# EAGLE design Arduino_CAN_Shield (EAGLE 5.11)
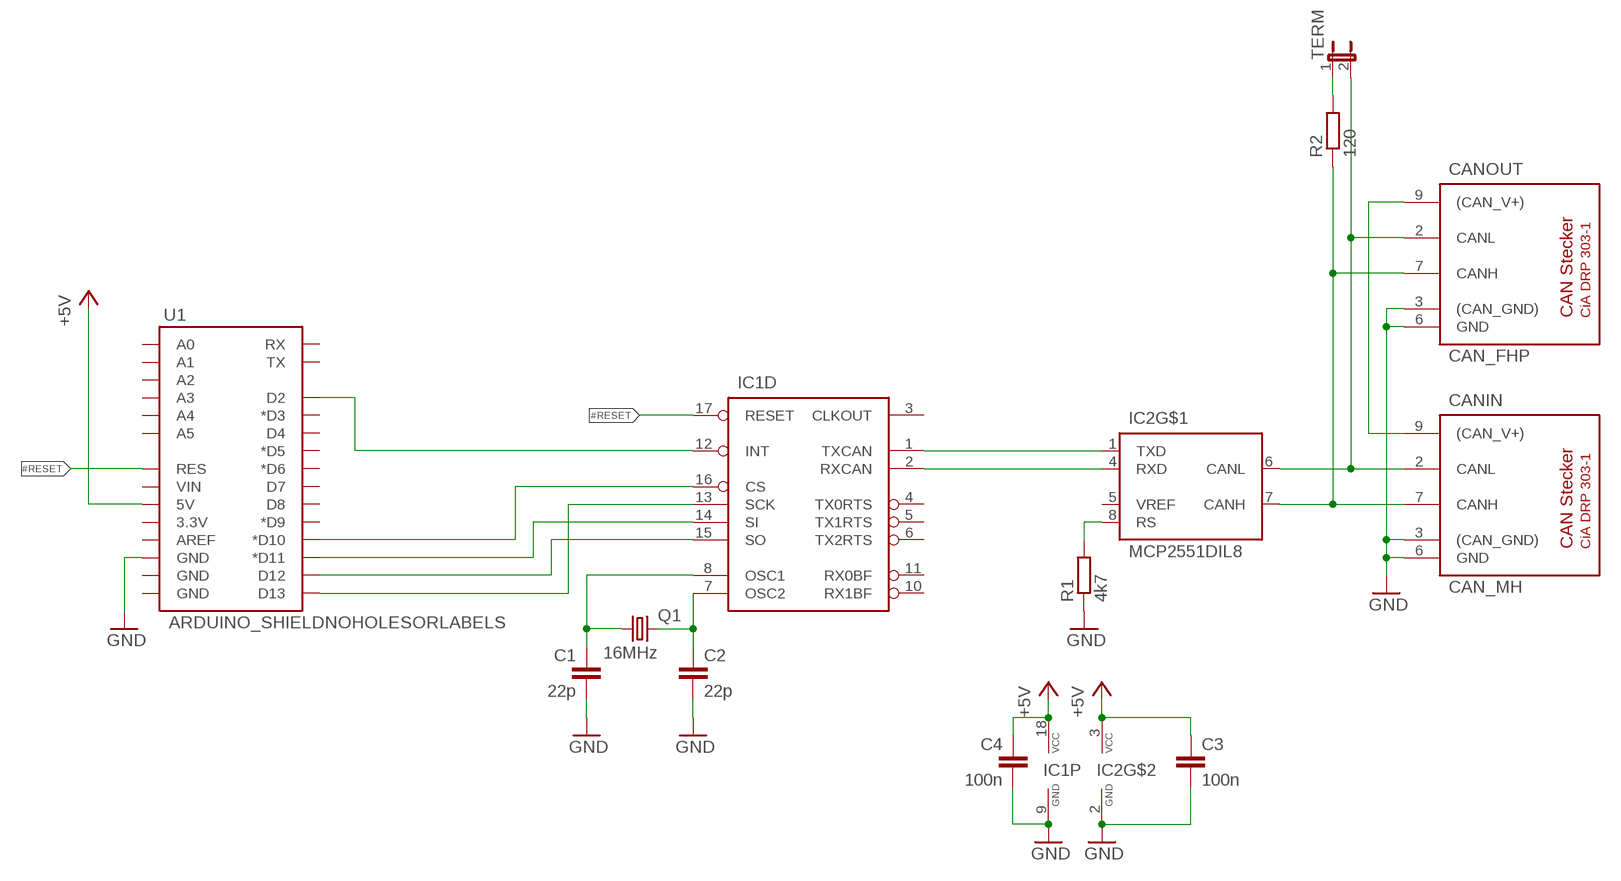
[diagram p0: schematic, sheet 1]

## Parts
C1  22p  C-EU025-024X044  [C025-024X044]
C2  22p  C-EU025-024X044  [C025-024X044]
C3  100n  C-EU025-025X050  [C025-025X050]
C4  100n  C-EU025-025X050  [C025-025X050]
CANIN  CAN_MH  [M09H]
CANOUT  CAN_FHP  [F09HP]
IC1  MCP2515P  [DIL18]
IC2  MCP2551DIL8  [DIL08]
Q1  16MHz  CRYSTALHC49S  [HC49/S]
R1  4k7  R-EU_0207/10  [0207/10]
R2  120  R-EU_0207/2V  [0207/2V]
TERM  JP1E  [JP1]
U1  ARDUINO_SHIELDNOHOLESORLABELS  [DUEMILANOVE_SHIELD_NOHOLES_NOLABELS]

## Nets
#RESET: IC1.17(D:RESET) U1.RES
+5V: C3.1 C4.1 IC1.18(P:VCC) IC2.3(VCC) U1.5V
GND: C1.2 C2.2 C3.2 C4.2 CANIN.3((CAN_GND)) CANIN.6(GND) CANOUT.3((CAN_GND)) CANOUT.6(GND) IC1.9(P:GND) IC2.2(GND) R1.1 U1.GND@2(GND)
N$1: CANIN.7(CANH) CANOUT.7(CANH) IC2.7(CANH) R2.1
N$2: CANIN.2(CANL) CANOUT.2(CANL) IC2.6(CANL) TERM.2
N$3: IC1.2(D:RXCAN) IC2.4(RXD)
N$4: IC1.13(D:SCK) U1.D13
N$5: IC1.15(D:SO) U1.D12
N$6: IC1.1(D:TXCAN) IC2.1(TXD)
N$7: IC1.14(D:SI) U1.D11(*D11)
N$8: IC1.16(D:CS) U1.D10(*D10)
N$9: C2.1 IC1.7(D:OSC2) Q1.2
N$10: C1.1 IC1.8(D:OSC1) Q1.1
N$11: IC1.12(D:INT) U1.D2
N$12: IC2.8(RS) R1.2
N$13: R2.2 TERM.1
N$14: CANIN.9((CAN_V+)) CANOUT.9((CAN_V+))
Unconnected: IC1.3(D:CLKOUT) IC1.4(D:TX0RTS) IC1.5(D:TX1RTS) IC1.6(D:TX2RTS) IC1.10(D:RX1BF) IC1.11(D:RX0BF) IC2.5(VREF) U1.3.3V U1.A0 U1.A1 U1.A2 U1.A3 U1.A4 U1.A5 U1.AREF U1.D3(*D3) U1.D4 U1.D5(*D5) U1.D6(*D6) U1.D7 U1.D8 U1.D9(*D9) U1.GND@0(GND) U1.GND@1(GND) U1.RX U1.TX U1.VIN

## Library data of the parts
C1-C4 = rcl:C-EU: CAPACITOR, European symbol
CANIN CANOUT = can:CAN_: CAN Stecker nach CiA DRP 303-1
IC1 = can:MCP2515: MC2515 Stand-Alone CAN Controller With SPI Interface, Microchip
IC2 = can:MCP2551: CAN Tranceiver Microchip
Q1 = crystal:CRYSTAL: CRYSTAL; OC_FARNELL: 1667008; OC_NEWARK: unknown
R1 R2 = rcl:R-EU_: RESISTOR, European symbol
TERM = jumper:JP1E: JUMPER
U1 = SparkFun:ARDUINO_SHIELD

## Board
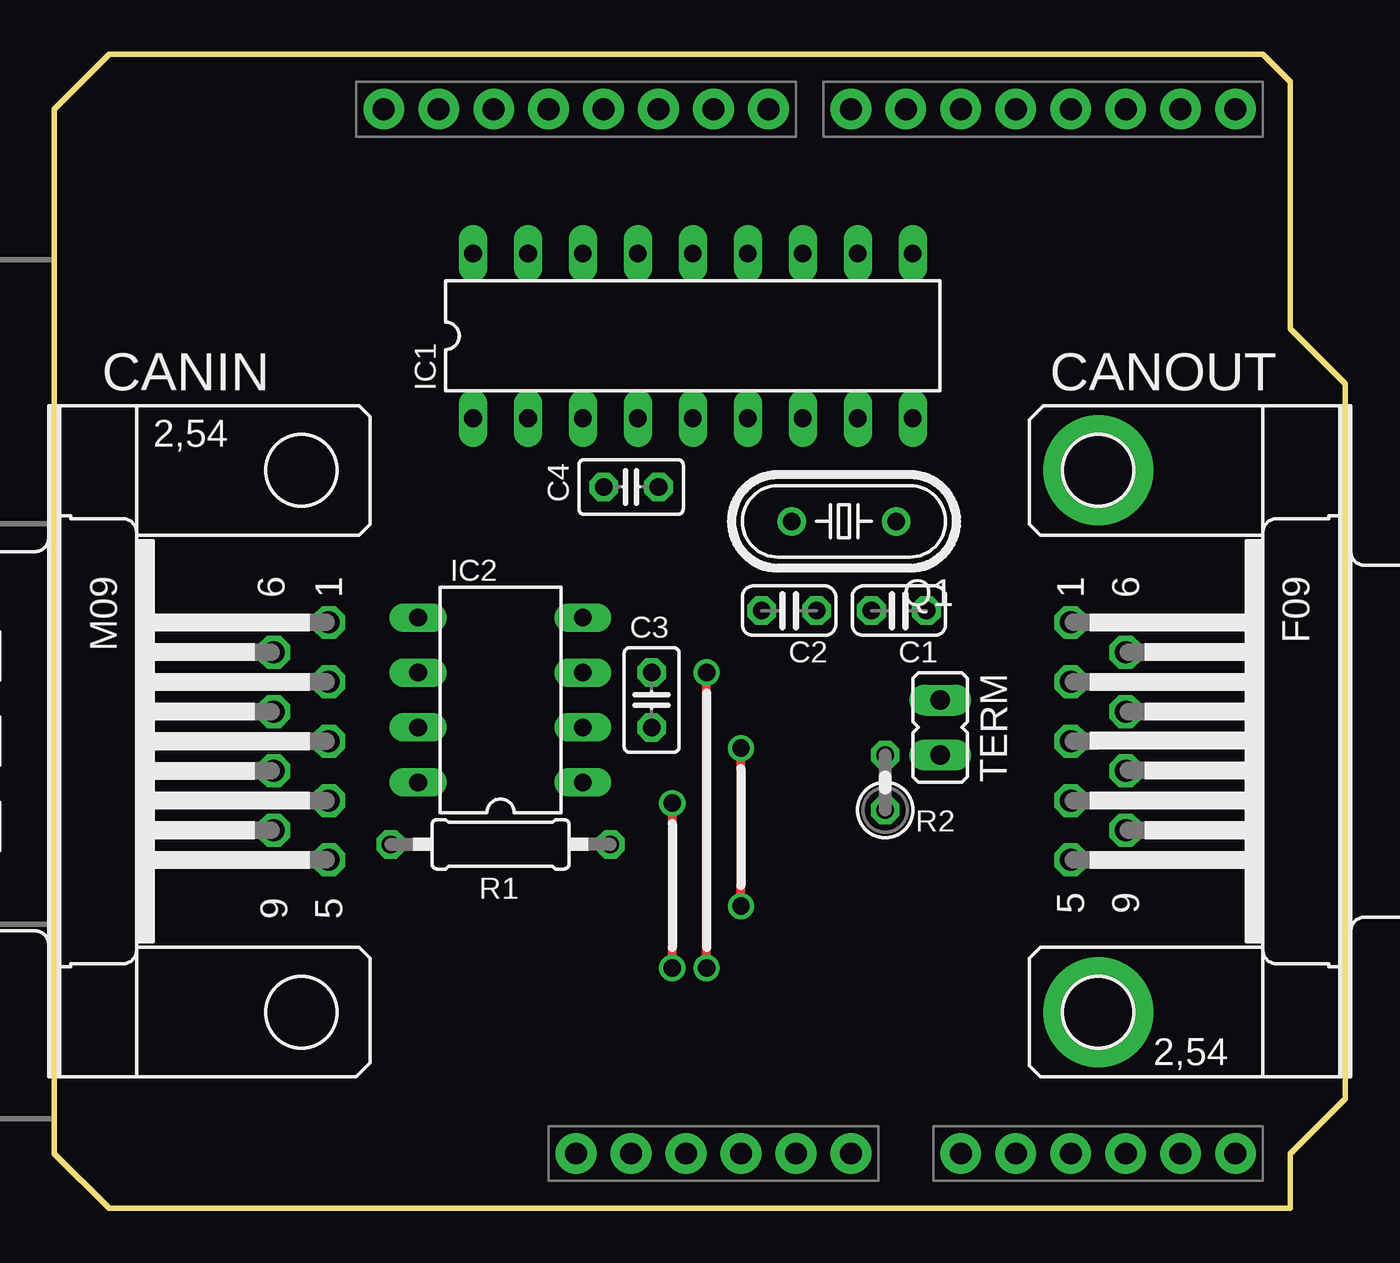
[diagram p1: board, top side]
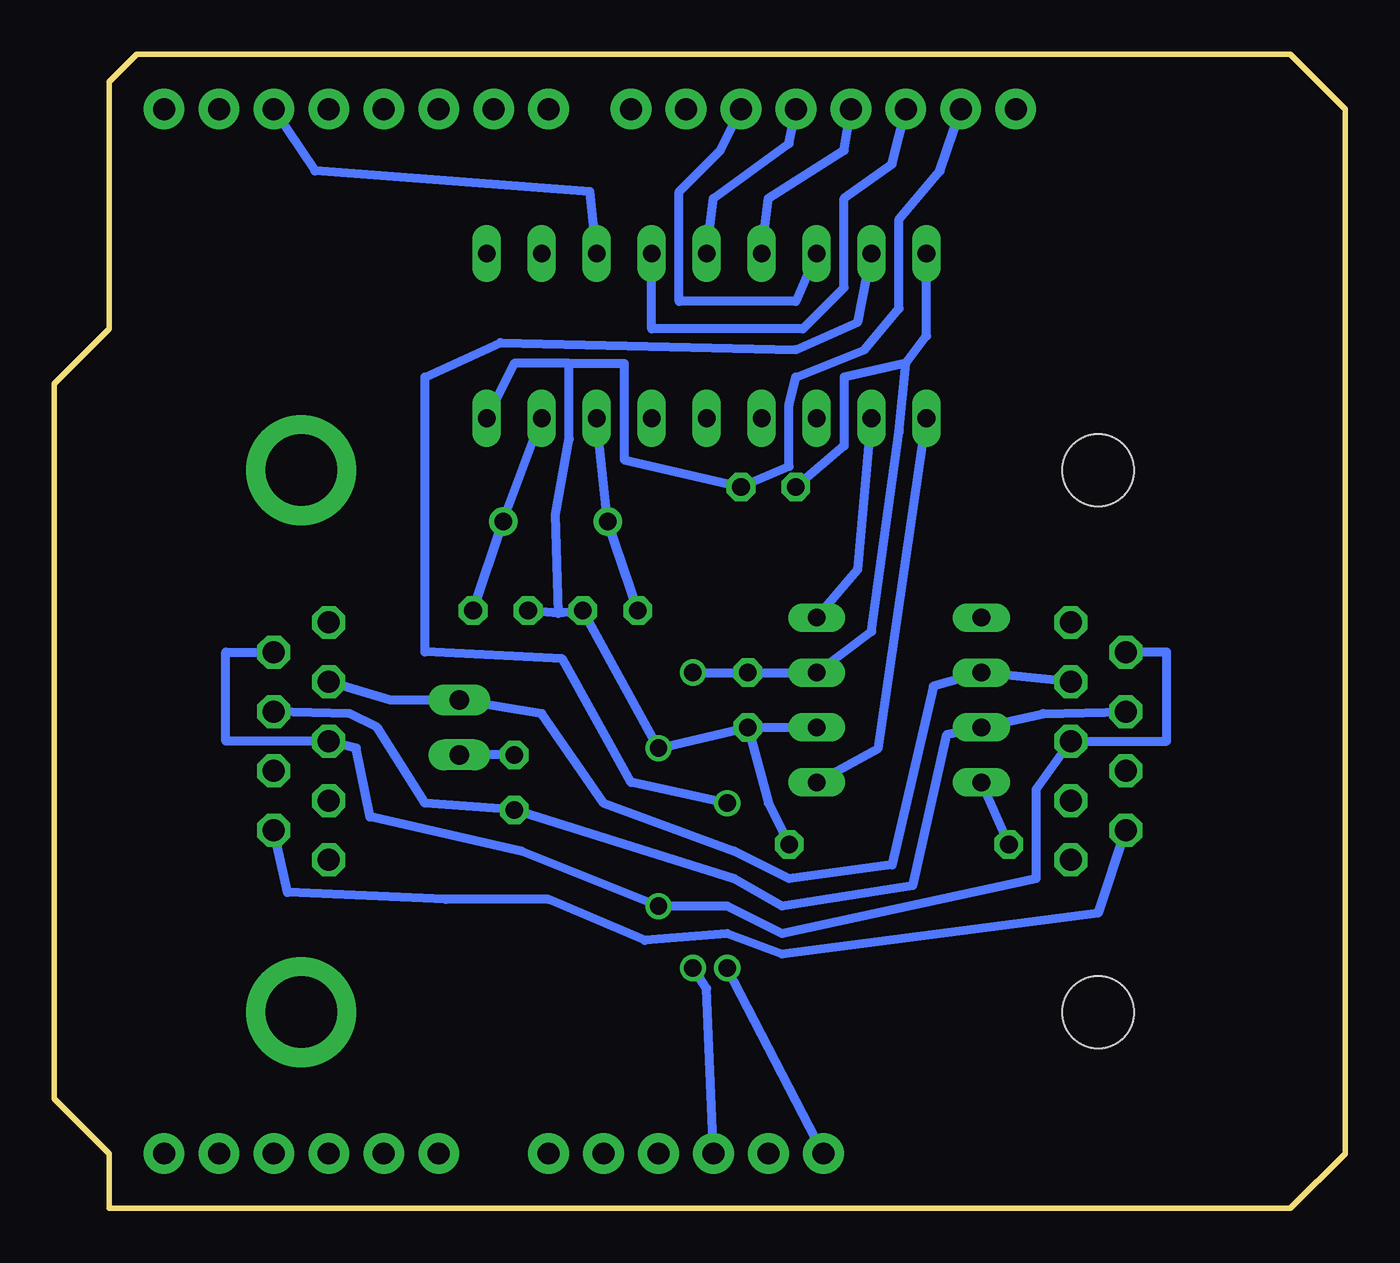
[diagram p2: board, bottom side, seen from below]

Size 59.69 x 53.34 mm. Coordinates in mm from the lower left corner, seen from the top.
Outline: 0,2.54 2.54,0 57.15,0 57.15,2.54 59.69,5.08 59.69,38.1 57.15,40.64 57.15,52.07 55.88,53.34 2.54,53.34 0,50.8 0,2.54
Copper layers (1*16): Top 0.035mm / dielectric 1.5mm / Bottom 0.035mm
Design rules "default": minimum track width 10mil, minimum drill 24mil, track to track 8mil, track to pad 8mil, pad to pad 8mil, via to via 8mil, smd to smd 8mil, copper to edge 40mil, drill to drill 8mil, minimum pad ring 10mil, minimum via ring 8mil, stop-mask expansion 4mil, vias tented up to drill 0mil, thermal gap 10mil

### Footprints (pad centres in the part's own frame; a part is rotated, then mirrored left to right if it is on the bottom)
C025-024X044 = drill 0.813 octagon: 1 -1.27,0; 2 1.27,0
C025-025X050 = drill 0.813 octagon: 1 -1.27,0; 2 1.27,0
M09H = drill 1.016 octagon: 1 -5.486,1.27; 2 -2.743,1.27; 3 0,1.27; 4 2.743,1.27; 5 5.486,1.27; 6 -4.115,-1.27; 7 -1.372,-1.27; 8 1.372,-1.27; 9 4.115,-1.27 | hole 3.302: 12.522,0; -12.522,0
F09HP = drill 1.016 octagon: 1 -5.486,-1.27; 2 -2.743,-1.27; 3 0,-1.27; 4 2.743,-1.27; 5 5.486,-1.27; 6 -4.115,1.27; 7 -1.372,1.27; 8 1.372,1.27; 9 4.115,1.27 | drill 3.302 pad 5.08 round: G1 -12.522,0; G2 12.522,0
DIL18 = drill 0.813 long: 1 -10.16,-3.81; 2 -7.62,-3.81; 3 -5.08,-3.81; 4 -2.54,-3.81; 5 0,-3.81; 6 2.54,-3.81; 7 5.08,-3.81; 8 7.62,-3.81; 9 10.16,-3.81; 10 10.16,3.81; 11 7.62,3.81; 12 5.08,3.81; 13 2.54,3.81; 14 0,3.81; 15 -2.54,3.81; 16 -5.08,3.81; 17 -7.62,3.81; 18 -10.16,3.81
DIL08 = drill 0.813 long: 1 -3.81,-3.81; 2 -1.27,-3.81; 3 1.27,-3.81; 4 3.81,-3.81; 5 3.81,3.81; 6 1.27,3.81; 7 -1.27,3.81; 8 -3.81,3.81
HC49/S = drill 0.813 round: 1 -2.413,0; 2 2.413,0
0207/10 = drill 0.813 octagon: 1 -5.08,0; 2 5.08,0
0207/2V = drill 0.813 octagon: 1 -1.27,0; 2 1.27,0
JP1 = drill 0.914 long: 1 0,-1.27; 2 0,1.27
DUEMILANOVE_SHIELD_NOHOLES_NOLABELS = drill 1.016 pad 1.88 round: 3.3V 50.8,26.67; 5V 50.8,29.21; A0 50.8,41.91; A1 50.8,44.45; A2 50.8,46.99; A3 50.8,49.53; A4 50.8,52.07; A5 50.8,54.61; AREF 2.54,15.24; D2 2.54,49.53; D3 2.54,46.99; D4 2.54,44.45; D5 2.54,41.91; D6 2.54,39.37; D7 2.54,36.83; D8 2.54,33.02; D9 2.54,30.48; D10 2.54,27.94; D11 2.54,25.4; D12 2.54,22.86; D13 2.54,20.32; GND@0 50.8,31.75; GND@1 50.8,34.29; GND@2 2.54,17.78; RES 50.8,24.13; RX 2.54,54.61; TX 2.54,52.07; VIN 50.8,36.83

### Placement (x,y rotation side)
C1  39.05,27.62 180 top
C2  33.97,27.62 0 top
C3  27.62,23.5 270 top
C4  26.67,33.34 0 top
CANIN  11.43,21.59 270 top
CANOUT  48.26,21.59 270 top
IC1  29.53,40.32 0 top
IC2  20.64,23.5 90 top
Q1  36.51,31.75 180 top
R1  20.64,16.83 180 top
R2  38.42,19.68 90 top
TERM  40.96,22.23 0 top
U1  0,53.34 270 top

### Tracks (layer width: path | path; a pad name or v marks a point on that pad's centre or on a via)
#RESET  (via drill 0.8)
  Top 0.406: v28.57,11.11 v28.57,18.73
  Bottom 0.406: IC1.17 22.54,40.96 25.4,39.69 39.05,40.01 42.55,38.42 42.55,25.72 36.2,25.4 33.02,19.68 v28.57,18.73 | U1.RES v28.57,11.11
+5V  (via drill 0.8)
  Top 0.406: v30.16,11.11 v30.16,24.77
  Bottom 0.406: U1.5V 29.53,10.16 v30.16,11.11 | v30.16,24.77 C3.1 IC2.3 21.91,26.67 20.64,35.88 20.32,39.05 | 20.32,39.05 19.37,40.32 IC1.18 | C4.1 23.18,35.24 23.18,38.42 20.32,39.05
GND  (via drill 0.8)
  Top 0.406: v31.75,13.97 v31.75,21.27
  Bottom 0.406: C3.2 IC2.2 | 36.38,27.5 36.51,32.07 35.88,35.56 35.88,39.05 | U1.GND@2 18.73,47.94 20.64,45.72 20.64,41.59 22.23,39.69 25.4,38.42 25.72,37.15 25.72,34.29 C4.2 33.34,34.61 33.34,39.05 35.88,39.05 | 35.88,39.05 38.42,39.05 IC1.9 | 36.38,27.5 C2.2 v31.75,21.27 C3.2 | 36.38,27.5 C1.2 | R1.1 26.67,18.73 C3.2 | CANIN.6 8.26,25.7 8.26,21.59 CANIN.3 14.29,19.37 14.29,15.24 26.04,12.7 28.57,13.97 v31.75,13.97 38.1,16.51 45.09,18.1 45.72,21.27 CANOUT.3 51.75,21.59 51.75,25.7 CANOUT.6
N$1
  Bottom 0.406: CANIN.7 13.97,22.86 IC2.7 18.41,21.91 20,14.92 26.04,13.97 28.26,15.24 R2.1 42.55,18.73 44.77,22.23 46.04,22.86 CANOUT.7
N$2
  Bottom 0.406: CANIN.2 IC2.6 19.05,24.13 20.95,15.88 25.72,15.24 28.26,16.51 34.29,18.73 37.15,22.86 TERM.2 44.13,23.5 CANOUT.2
N$3
  Bottom 0.406: IC2.4 22.54,29.53 IC1.2
N$4
  Bottom 0.406: U1.D13 20.95,48.26 23.18,46.67 23.18,42.55 25.08,40.64 32.07,40.64 IC1.13
N$5
  Bottom 0.406: U1.D12 23.18,48.9 26.67,46.67 IC1.15
N$6
  Bottom 0.406: IC2.1 21.59,21.27 IC1.1
N$7
  Bottom 0.406: U1.D11 25.72,49.21 29.21,46.67 IC1.14
N$8
  Bottom 0.406: IC1.16 25.4,41.91 30.8,41.91 30.8,46.99 28.89,48.9 U1.D10
N$9
  Bottom 0.406: IC1.7 Q1.2 C2.1
N$10
  Bottom 0.406: IC1.8 Q1.1 C1.1
N$11
  Bottom 0.406: IC1.12 34.92,46.99 47.62,47.94 U1.D2
N$12
  Bottom 0.406: R1.2 IC2.8
N$13
  Bottom 0.406: R2.2 TERM.1
N$14
  Bottom 0.406: CANIN.9 11.43,13.65 26.04,11.75 28.57,12.7 32.38,12.38 36.83,14.29 41.59,14.29 48.9,14.61 CANOUT.9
